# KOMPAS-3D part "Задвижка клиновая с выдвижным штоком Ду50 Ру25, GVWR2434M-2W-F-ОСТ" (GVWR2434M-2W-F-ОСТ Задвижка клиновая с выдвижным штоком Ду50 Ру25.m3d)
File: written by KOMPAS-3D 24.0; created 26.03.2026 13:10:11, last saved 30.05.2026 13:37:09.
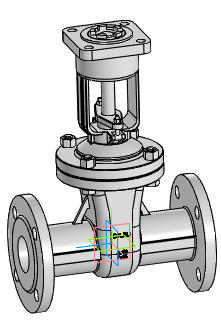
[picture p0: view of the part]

Document properties: Автор: R2D2; Полное имя файла: E:\Работа\Зайцев\GVWR2434M-2W-F-ОСТ Задвижка клиновая с выдвижным штоком DN.ru Ду50-300 Ру25\исходные материалы\DN50\DN50\GVWR2434M-2W-F-ОСТ Задвижка клиновая с выдвижным штоком Ду50 Ру25.m3d

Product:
- Part/product: Задвижка клиновая с выдвижным штоком Ду50 Ру25  | designation GVWR2434M-2W-F-ОСТ
    Масса: 13
    Раздел спецификации: Прочие изделия
    Примечание: D040-07586

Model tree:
1. Операция без истории:1

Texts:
  GVWR2434M-2W-F-ОСТ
